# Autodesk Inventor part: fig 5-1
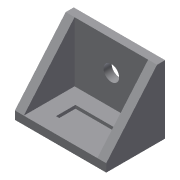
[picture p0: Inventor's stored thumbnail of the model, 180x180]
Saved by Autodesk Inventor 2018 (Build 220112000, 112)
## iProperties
Created: 2012-07
Part Number: fig 5-1
Material: Generic
Document SubType Name: Modeling
Designer: CADCIM
Density: 1 g/cm^3
Appearance: Default
Author: CADCIM
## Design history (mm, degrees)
sketch "Sketch1"
  geometry: L1 (-14.1, 7.837)-(14.1, 7.837); L2 (14.1, 7.837)-(14.1, -7.837); L3 (14.1, -7.837)-(-14.1, -7.837); L4 (-14.1, -7.837)-(-14.1, 7.837); L5 (-14.1, 7.837)-(14.1, -7.837); L6 (14.1, 7.837)-(-14.1, -7.837); 1 further point
  constraints: 12 end point, 2 midpoint, 2 parallel, 1 horizontal, 1 perpendicular
extrude "Extrusion1" new body sketch "Sketch1" distance "d0" = 2.5; taper "d1" = 0 deg
sketch "Sketch2"
  geometry: L1 (0, -20.969)-(28.201, -20.969); L2 (28.201, -20.969)-(28.201, 0); L3 (28.201, 0)-(0, 0); L4 (0, 0)-(0, -20.969); L5 (0, -20.969)-(28.201, 0); L6 (28.201, -20.969)-(0, 0); 1 further point
  constraints: 12 end point, 2 midpoint, 2 parallel, 1 horizontal, 1 perpendicular
extrude "Extrusion2" join sketch "Sketch2" distance "d2" = 2.5; taper "d3" = 0 deg
sketch "Sketch3"
  geometry: L1 (-6.24, 3)-(6.24, 3); L2 (6.24, 3)-(6.24, -3); L3 (6.24, -3)-(-6.24, -3); L4 (-6.24, -3)-(-6.24, 3); L5 (-6.24, 3)-(6.24, -3); L6 (6.24, 3)-(-6.24, -3); 1 further point
  constraints: 12 end point, 2 midpoint, 2 parallel, 1 horizontal, 1 perpendicular
extrude "Extrusion3" cut sketch "Sketch3" distance "d4" = 1; taper "d5" = 0 deg
sketch "Sketch4"
  geometry: L1 (2.5, 18.174)-(2.5, 0) reference; L2 (-18.469, 15.674)-(0, 15.674) reference; L3 (-18.469, 15.674)-(0, 0); L4 (-18.469, 15.674)-(0, 15.674); L5 (0, 0)-(0, 15.674)
  constraints: 6 end point, 1 collinear, 1 parallel
extrude "Extrusion4" join sketch "Sketch4" distance "d6" = 2.75; taper "d7" = 0 deg
mirror "Mirror1"
sketch "Sketch5"
  geometry: C1 r 2.409 at (14.1, 11.735)
  constraints: 1 centre point
extrude "Extrusion5" cut sketch "Sketch5" distance "d8" = 2.75; taper "d9" = 0 deg
body "Solid1"
